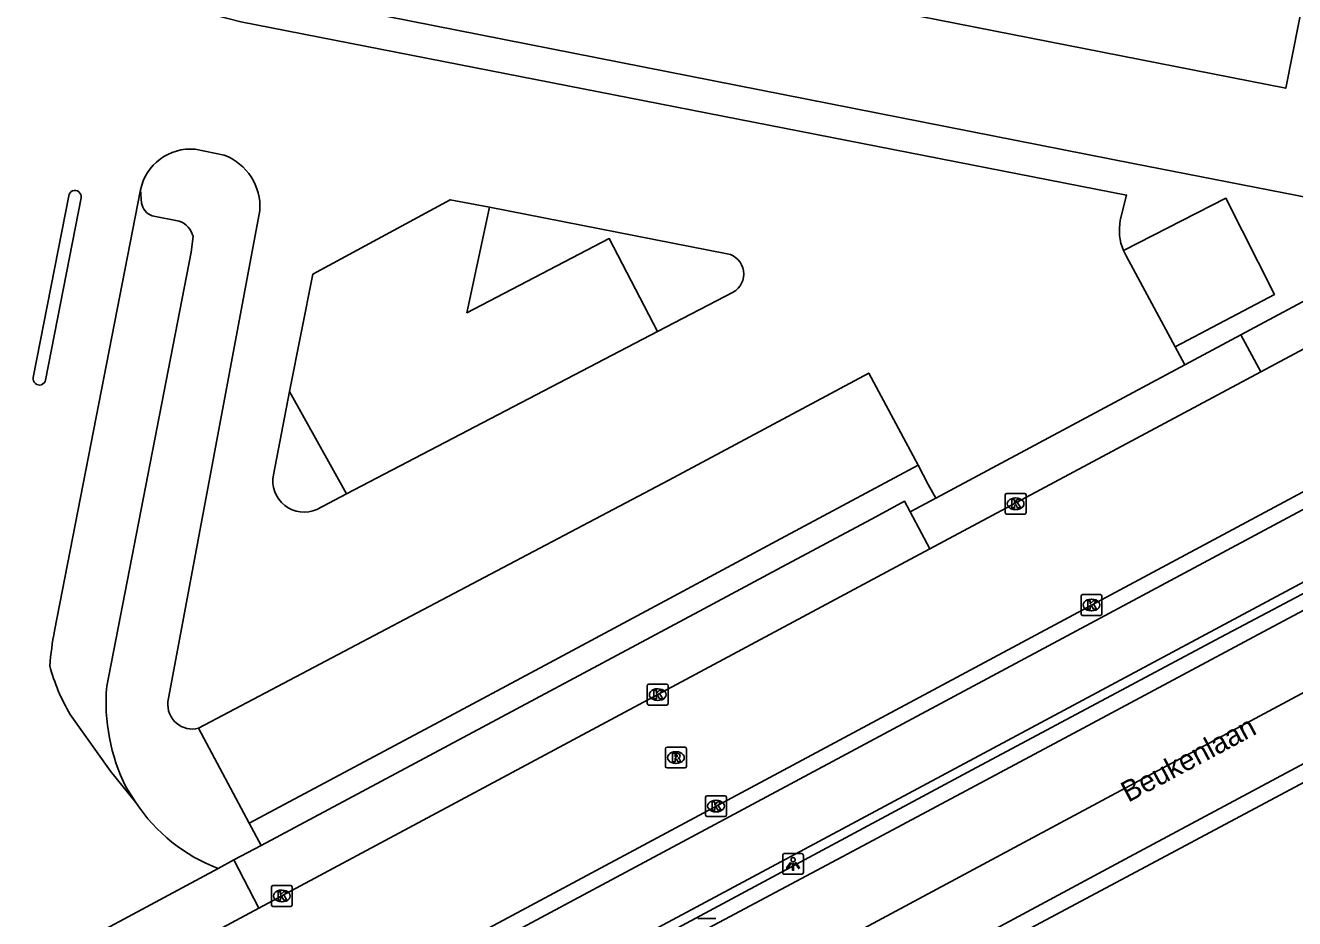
# Model space of a CAD drawing. Extents: x 158797 to 159887, y 384318 to 385255.
# Drawn here: x 159597.2 to 159658.1, y 384405.2 to 384448.1 of the extents above; entities that cross this region are included whole.
import ezdxf

# ---------------------------------------------------------------- set-up
doc = ezdxf.new("R2010")
doc.units = 0
for name, color, linetype in [('IMGEO_Berm_open', 7, 'Continuous'), ('IMGEO_Fietspad_gesloten', 7, 'Continuous'), ('IMGEO_Kolk', 7, 'Continuous'), ('IMGEO_Lichtpunt', 7, 'Continuous'), ('IMGEO_Openbare_ruimte_label', 7, 'Continuous'), ('IMGEO_Pand', 7, 'Continuous'), ('IMGEO_Parkeervlak_open', 7, 'Continuous'), ('IMGEO_Rijbaan_lokaal_gesloten', 7, 'Continuous'), ('IMGEO_Rijbaan_regionaal_gesloten', 7, 'Continuous'), ('IMGEO_Rioolput', 7, 'Continuous'), ('IMGEO_Voetpad_open', 7, 'Continuous')]:
    doc.layers.add(name, color=color, linetype=linetype)

msp = doc.modelspace()

# ---------------------------------------------------------------- linework, layer by layer
at = {"layer": 'IMGEO_Berm_open'}
msp.add_lwpolyline([(159693.288, 384438.625), (159692.958, 384439.23), (159683.971, 384434.448), (159672.561, 384428.328), (159664.238, 384423.844), (159654.268, 384418.57), (159642.609, 384412.337), (159624.993, 384402.897), (159622.895, 384401.766), (159617.171, 384398.703), (159613.053, 384396.512)], dxfattribs=at)
at = {"layer": 'IMGEO_Fietspad_gesloten'}
for points in [[(159707.394, 384451.026), (159691.341, 384442.43), (159554.532, 384369.175), (159553.562, 384368.656)], [(159705.22, 384446.356), (159692.734, 384439.673), (159612.839, 384396.912)]]:
    msp.add_lwpolyline(points, dxfattribs=at)
at = {"layer": 'IMGEO_Kolk'}
for p, q in [((159644.191, 384424.683), (159644.191, 384425.535)), ((159644.266, 384425.609), (159645.118, 384425.609)), ((159645.192, 384425.535), (159645.192, 384424.683)), ((159644.679, 384425.389), (159644.704, 384425.389)), ((159645.118, 384424.609), (159644.266, 384424.609)), ((159644.702, 384424.829), (159644.677, 384424.829)), ((159647.831, 384419.827), (159647.831, 384420.679)), ((159647.906, 384420.753), (159648.758, 384420.753)), ((159648.832, 384420.679), (159648.832, 384419.827)), ((159648.342, 384419.973), (159648.317, 384419.973)), ((159648.319, 384420.533), (159648.344, 384420.533)), ((159648.758, 384419.753), (159647.906, 384419.753)), ((159627.019, 384415.527), (159627.019, 384416.379)), ((159627.094, 384416.453), (159627.946, 384416.453)), ((159628.02, 384416.379), (159628.02, 384415.527)), ((159627.507, 384416.233), (159627.532, 384416.233)), ((159627.946, 384415.453), (159627.094, 384415.453)), ((159627.53, 384415.673), (159627.505, 384415.673)), ((159629.815, 384410.178), (159629.815, 384411.03)), ((159629.89, 384411.104), (159630.742, 384411.104)), ((159630.303, 384410.884), (159630.328, 384410.884)), ((159630.816, 384411.03), (159630.816, 384410.178)), ((159630.326, 384410.324), (159630.301, 384410.324)), ((159630.742, 384410.104), (159629.89, 384410.104)), ((159608.982, 384405.867), (159608.982, 384406.719)), ((159609.057, 384406.793), (159609.909, 384406.793)), ((159609.983, 384406.719), (159609.983, 384405.867)), ((159609.493, 384406.013), (159609.468, 384406.013)), ((159609.47, 384406.573), (159609.495, 384406.573)), ((159609.909, 384405.793), (159609.057, 384405.793)), ((159629.45, 384405.206), (159630.302, 384405.206))]:
    msp.add_line(p, q, dxfattribs=at)
for points in [[(159644.191, 384424.683), (159644.191, 384425.535)], [(159644.266, 384425.609), (159645.118, 384425.609)], [(159645.192, 384425.535), (159645.192, 384424.683)], [(159644.512, 384425.309), (159644.635, 384425.309), (159644.635, 384425.158), (159644.765, 384425.309), (159644.929, 384425.309), (159644.783, 384425.158), (159644.936, 384424.909), (159644.784, 384424.909), (159644.699, 384425.073), (159644.635, 384425.006), (159644.635, 384424.909), (159644.512, 384424.909), (159644.512, 384425.309)], [(159645.118, 384424.609), (159644.266, 384424.609)], [(159647.831, 384419.827), (159647.831, 384420.679)], [(159647.906, 384420.753), (159648.758, 384420.753)], [(159648.832, 384420.679), (159648.832, 384419.827)], [(159648.152, 384420.453), (159648.275, 384420.453), (159648.275, 384420.302), (159648.405, 384420.453), (159648.569, 384420.453), (159648.423, 384420.302), (159648.576, 384420.053), (159648.424, 384420.053), (159648.339, 384420.217), (159648.275, 384420.15), (159648.275, 384420.053), (159648.152, 384420.053), (159648.152, 384420.453)], [(159648.758, 384419.753), (159647.906, 384419.753)], [(159627.019, 384415.527), (159627.019, 384416.379)], [(159627.094, 384416.453), (159627.946, 384416.453)], [(159628.02, 384416.379), (159628.02, 384415.527)], [(159627.34, 384416.153), (159627.463, 384416.153), (159627.463, 384416.002), (159627.593, 384416.153), (159627.757, 384416.153), (159627.611, 384416.002), (159627.764, 384415.753), (159627.612, 384415.753), (159627.527, 384415.917), (159627.463, 384415.85), (159627.463, 384415.753), (159627.34, 384415.753), (159627.34, 384416.153)], [(159627.946, 384415.453), (159627.094, 384415.453)], [(159629.815, 384410.178), (159629.815, 384411.03)], [(159629.89, 384411.104), (159630.742, 384411.104)], [(159630.816, 384411.03), (159630.816, 384410.178)], [(159630.136, 384410.804), (159630.259, 384410.804), (159630.259, 384410.653), (159630.389, 384410.804), (159630.553, 384410.804), (159630.407, 384410.653), (159630.56, 384410.404), (159630.408, 384410.404), (159630.323, 384410.568), (159630.259, 384410.501), (159630.259, 384410.404), (159630.136, 384410.404), (159630.136, 384410.804)], [(159630.742, 384410.104), (159629.89, 384410.104)], [(159608.982, 384405.867), (159608.982, 384406.719)], [(159609.057, 384406.793), (159609.909, 384406.793)], [(159609.983, 384406.719), (159609.983, 384405.867)], [(159609.303, 384406.493), (159609.426, 384406.493), (159609.426, 384406.342), (159609.556, 384406.493), (159609.72, 384406.493), (159609.574, 384406.342), (159609.727, 384406.093), (159609.575, 384406.093), (159609.49, 384406.257), (159609.426, 384406.19), (159609.426, 384406.093), (159609.303, 384406.093), (159609.303, 384406.493)], [(159609.909, 384405.793), (159609.057, 384405.793)], [(159629.45, 384405.206), (159630.302, 384405.206)]]:
    msp.add_lwpolyline(points, dxfattribs=at)
for centre, start, end in [((159644.268, 384425.533), 91.55205, 178.44795), ((159644.268, 384425.533), 91.55205, 178.44795), ((159645.116, 384425.533), 1.55205, 88.44795), ((159645.116, 384425.533), 1.55205, 88.44795), ((159644.268, 384424.685), 181.55205, 268.44795), ((159644.268, 384424.685), 181.55205, 268.44795), ((159645.116, 384424.685), 271.55205, 358.44795), ((159645.116, 384424.685), 271.55205, 358.44795), ((159647.908, 384420.677), 91.55205, 178.44795), ((159647.908, 384420.677), 91.55205, 178.44795), ((159648.756, 384420.677), 1.55205, 88.44795), ((159648.756, 384420.677), 1.55205, 88.44795), ((159647.908, 384419.829), 181.55205, 268.44795), ((159647.908, 384419.829), 181.55205, 268.44795), ((159648.756, 384419.829), 271.55205, 358.44795), ((159648.756, 384419.829), 271.55205, 358.44795), ((159627.096, 384416.377), 91.55205, 178.44795), ((159627.096, 384416.377), 91.55205, 178.44795), ((159627.944, 384416.377), 1.55205, 88.44795), ((159627.944, 384416.377), 1.55205, 88.44795), ((159627.096, 384415.529), 181.55205, 268.44795), ((159627.096, 384415.529), 181.55205, 268.44795), ((159627.944, 384415.529), 271.55205, 358.44795), ((159627.944, 384415.529), 271.55205, 358.44795), ((159629.892, 384411.028), 91.55205, 178.44795), ((159629.892, 384411.028), 91.55205, 178.44795), ((159630.74, 384411.028), 1.55205, 88.44795), ((159630.74, 384411.028), 1.55205, 88.44795), ((159629.892, 384410.18), 181.55205, 268.44795), ((159629.892, 384410.18), 181.55205, 268.44795), ((159630.74, 384410.18), 271.55205, 358.44795), ((159630.74, 384410.18), 271.55205, 358.44795), ((159609.059, 384406.717), 91.55205, 178.44795), ((159609.059, 384406.717), 91.55205, 178.44795), ((159609.907, 384406.717), 1.55205, 88.44795), ((159609.907, 384406.717), 1.55205, 88.44795), ((159609.059, 384405.869), 181.55205, 268.44795), ((159609.059, 384405.869), 181.55205, 268.44795), ((159609.907, 384405.869), 271.55205, 358.44795), ((159609.907, 384405.869), 271.55205, 358.44795)]:
    msp.add_arc(centre, 0.0765, start, end, dxfattribs=at)
for centre, major_axis, ratio, start_param, end_param in [((159644.678, 384425.109), (-0.387, 0.002), 0.722429, 4.712389, 7.853982), ((159644.703, 384425.109), (-0.39, 0.002), 0.717154, 1.570796, 4.712389), ((159648.318, 384420.253), (-0.387, 0.002), 0.722429, 4.712389, 7.853982), ((159648.343, 384420.253), (-0.39, 0.002), 0.717154, 1.570796, 4.712389), ((159627.506, 384415.953), (-0.387, 0.002), 0.722429, 4.712389, 7.853982), ((159627.531, 384415.953), (-0.39, 0.002), 0.717154, 1.570796, 4.712389), ((159630.302, 384410.604), (-0.387, 0.002), 0.722429, 4.712389, 7.853982), ((159630.327, 384410.604), (-0.39, 0.002), 0.717154, 1.570796, 4.712389), ((159609.469, 384406.293), (-0.387, 0.002), 0.722429, 4.712389, 7.853982), ((159609.494, 384406.293), (-0.39, 0.002), 0.717154, 1.570796, 4.712389)]:
    msp.add_ellipse(centre, major_axis=major_axis, ratio=ratio, start_param=start_param, end_param=end_param, dxfattribs=at)
at = {"layer": 'IMGEO_Lichtpunt'}
for p, q in [((159633.516, 384408.236), (159633.516, 384407.429)), ((159633.516, 384408.236), (159633.516, 384407.429)), ((159634.418, 384408.331), (159633.61, 384408.331)), ((159634.418, 384408.331), (159633.61, 384408.331)), ((159634.512, 384407.429), (159634.512, 384408.236)), ((159634.512, 384407.429), (159634.512, 384408.236)), ((159633.61, 384407.335), (159634.418, 384407.335)), ((159633.61, 384407.335), (159634.418, 384407.335))]:
    msp.add_line(p, q, dxfattribs=at)
for points in [[(159633.89, 384407.9), (159633.929, 384407.872), (159633.741, 384407.61), (159633.703, 384407.637), (159633.89, 384407.9)], [(159633.992, 384407.852), (159634.039, 384407.852), (159634.039, 384407.53), (159633.992, 384407.53), (159633.992, 384407.852)], [(159634.102, 384407.872), (159634.14, 384407.899), (159634.327, 384407.637), (159634.288, 384407.609), (159634.102, 384407.872)]]:
    msp.add_lwpolyline(points, dxfattribs=at)
msp.add_circle((159634.015, 384408.034), 0.0994, dxfattribs=at)
for centre, start, end in [((159633.61, 384408.236), 90, 180), ((159633.61, 384408.236), 90, 180), ((159634.418, 384408.236), 0, 90), ((159634.418, 384408.236), 0, 90), ((159633.61, 384407.429), 180, 270), ((159633.61, 384407.429), 180, 270), ((159634.418, 384407.429), 270, 0), ((159634.418, 384407.429), 270, 360)]:
    msp.add_arc(centre, 0.0946, start, end, dxfattribs=at)
at = {"layer": 'IMGEO_Pand'}
msp.add_lwpolyline([(159615.168, 384493.218), (159631.646, 384489.94), (159631.594, 384489.43), (159642.299, 384487.34), (159642.371, 384487.828), (159663.172, 384483.741), (159663.062, 384483.15), (159665.104, 384482.719), (159657.652, 384445.044), (159634.856, 384449.536), (159634.884, 384450.102), (159624.284, 384452.245), (159624.125, 384451.684), (159608.374, 384454.809), (159607.652, 384454.952)], dxfattribs=at)
at = {"layer": 'IMGEO_Parkeervlak_open'}
msp.add_lwpolyline([(159640.014, 384426.956), (159633.201, 384423.308), (159628.746, 384420.922), (159622.319, 384417.481), (159616.58, 384414.408), (159607.921, 384409.781)], dxfattribs=at)
at = {"layer": 'IMGEO_Rijbaan_lokaal_gesloten'}
for points in [[(159553.184, 384369.293), (159691, 384443.105), (159706.671, 384451.498)], [(159649.715, 384438.714), (159650.018, 384439.921), (159607.516, 384448.232), (159606.273, 384448.548)], [(159656.463, 384431.445), (159663.602, 384435.266), (159667.341, 384437.251), (159683.468, 384445.886)], [(159605.321, 384442.122), (159606.717, 384441.837)], [(159598.577, 384419.017), (159602.701, 384440.173)], [(159597.56, 384431.163), (159599.256, 384439.891)], [(159599.848, 384439.793), (159598.148, 384431.047)], [(159609.858, 384430.49), (159610.974, 384436.129), (159617.567, 384439.692), (159619.441, 384439.334)], [(159608.429, 384439.174), (159604.02, 384415.601)], [(159619.441, 384439.334), (159630.857, 384437.108)], [(159652.339, 384432.641), (159649.99, 384437.008), (159649.866, 384437.26)], [(159631.136, 384435.258), (159627.514, 384433.369)], [(159627.514, 384433.369), (159612.594, 384425.584)], [(159652.805, 384431.774), (159652.339, 384432.641)], [(159640.859, 384425.377), (159652.805, 384431.774)], [(159605.487, 384414.336), (159615.678, 384419.713), (159628.056, 384426.244), (159637.645, 384431.379), (159640.014, 384426.956)], [(159640.576, 384422.941), (159656.463, 384431.445)], [(159609.082, 384426.497), (159609.858, 384430.49)], [(159640.014, 384426.956), (159640.503, 384426.042), (159640.859, 384425.377)], [(159612.594, 384425.584), (159611.17, 384424.84)], [(159640.576, 384422.941), (159639.863, 384422.559), (159627.52, 384415.953), (159609.483, 384406.293), (159608.385, 384405.705)], [(159602.483, 384410.773), (159601.258, 384412.276), (159599.333, 384415.004)], [(159588.06, 384397.767), (159606.423, 384407.612)], [(159578.043, 384389.447), (159608.385, 384405.705)]]:
    msp.add_lwpolyline(points, dxfattribs=at)
for centre, radius, start, end in [((159605.114, 384439.664), 2.466, 85.19294, 168.09767), ((159605.774, 384439.349), 2.661, 356.23152, 69.24111), ((159599.552, 384439.842), 0.3, 350.60047, 170.60047), ((159652.187, 384438.236), 2.518, 169.05592, 202.80207), ((159630.646, 384436.13), 1, 299.34748, 77.80491), ((159597.854, 384431.105), 0.3, 168.84006, 348.84006), ((159610.555, 384426.209), 1.501, 168.91852, 294.21169), ((159614.072, 384416.048), 15.777, 169.15492, 175.3117), ((159607.169, 384419.686), 9.129, 194.90487, 210.85679), ((159605.191, 384415.475), 1.177, 173.87632, 284.58102), ((159609.335, 384415.278), 8.2, 213.32244, 249.19851)]:
    msp.add_arc(centre, radius, start, end, dxfattribs=at)
at = {"layer": 'IMGEO_Rijbaan_regionaal_gesloten'}
for points in [[(159880.669, 384532.909), (159875.798, 384530.374), (159847.424, 384515.674), (159804.811, 384493.696), (159779.976, 384480.85), (159750.919, 384465.55), (159708.655, 384442.945), (159694.585, 384435.384), (159645.738, 384409.21), (159615.068, 384392.753)], [(159616.488, 384390.102), (159630.958, 384397.851), (159650.153, 384408.169), (159667.67, 384417.548), (159686.549, 384427.613), (159696.214, 384432.791), (159709.47, 384439.893), (159725.249, 384448.362), (159745.061, 384458.917), (159759.449, 384466.649), (159775.497, 384475.211), (159791.41, 384483.447), (159811.928, 384494.056), (159823.458, 384500), (159870.864, 384524.44), (159874.443, 384526.273), (159882.662, 384530.596)], [(159883.694, 384529.35), (159881.307, 384528.22), (159875.887, 384525.604), (159825.453, 384500), (159812.356, 384493.351), (159791.799, 384482.795), (159777.564, 384475.395), (159744.535, 384457.751), (159731.675, 384450.855), (159717.186, 384443.101), (159697.88, 384432.802), (159696.562, 384432.097), (159679.569, 384423.013), (159661.921, 384413.563), (159644.473, 384404.254), (159631.206, 384397.094), (159616.87, 384389.389)], [(159693.288, 384438.625), (159687.108, 384435.294), (159673.007, 384427.734), (159656.81, 384419.099), (159647.237, 384413.981), (159637.604, 384408.821), (159626.551, 384402.935), (159617.694, 384398.165), (159613.635, 384395.988), (159613.401, 384395.863)]]:
    msp.add_lwpolyline(points, dxfattribs=at)
at = {"layer": 'IMGEO_Rioolput'}
for p, q in [((159627.893, 384412.507), (159627.893, 384413.359)), ((159627.968, 384413.433), (159628.82, 384413.433)), ((159628.894, 384413.359), (159628.894, 384412.507)), ((159628.381, 384413.213), (159628.406, 384413.213)), ((159628.82, 384412.433), (159627.968, 384412.433)), ((159628.404, 384412.653), (159628.379, 384412.653))]:
    msp.add_line(p, q, dxfattribs=at)
for points in [[(159627.893, 384412.507), (159627.893, 384413.359)], [(159627.968, 384413.433), (159628.82, 384413.433)], [(159628.894, 384413.359), (159628.894, 384412.507)], [(159628.482, 384413.131), (159628.23, 384413.133), (159628.23, 384412.733)], [(159628.23, 384412.733), (159628.354, 384412.733), (159628.354, 384412.895), (159628.365, 384412.895)], [(159628.408, 384413.052), (159628.354, 384413.052), (159628.354, 384412.971)], [(159628.354, 384412.971), (159628.406, 384412.971)], [(159628.412, 384412.866), (159628.483, 384412.733), (159628.623, 384412.733), (159628.558, 384412.859)], [(159628.82, 384412.433), (159627.968, 384412.433)]]:
    msp.add_lwpolyline(points, dxfattribs=at)
for centre, radius, start, end in [((159627.97, 384413.357), 0.0765, 91.55205, 178.44795), ((159627.97, 384413.357), 0.0765, 91.55205, 178.44795), ((159628.818, 384413.357), 0.0765, 1.55205, 88.44795), ((159628.818, 384413.357), 0.0765, 1.55205, 88.44795), ((159628.364, 384412.842), 0.0533, 26.02933, 88.69889), ((159628.39, 384413.16), 0.19, 274.7715, 282.96867), ((159628.414, 384412.956), 0.0964, 77.00612, 93.18647), ((159628.428, 384413.013), 0.0378, 276.66336, 79.67722), ((159628.481, 384413.021), 0.109, 350.36119, 89.41601), ((159628.479, 384413.021), 0.112, 277.58423, 350.98172), ((159628.463, 384412.806), 0.108, 29.51342, 73.79051), ((159627.97, 384412.509), 0.0765, 181.55205, 268.44795), ((159627.97, 384412.509), 0.0765, 181.55205, 268.44795), ((159628.818, 384412.509), 0.0765, 271.55205, 358.44795), ((159628.818, 384412.509), 0.0765, 271.55205, 358.44795)]:
    msp.add_arc(centre, radius, start, end, dxfattribs=at)
for centre, major_axis, ratio, start_param, end_param in [((159628.38, 384412.933), (-0.387, 0.002), 0.722429, 4.712389, 7.853982), ((159628.405, 384412.933), (-0.39, 0.002), 0.717154, 1.570796, 4.712389)]:
    msp.add_ellipse(centre, major_axis=major_axis, ratio=ratio, start_param=start_param, end_param=end_param, dxfattribs=at)
at = {"layer": 'IMGEO_Voetpad_open'}
for points in [[(159607.652, 384454.952), (159606.689, 384450.048), (159650.339, 384441.442), (159664.679, 384438.637), (159682.172, 384447.751), (159682.698, 384450.091), (159679.597, 384455.98), (159680.012, 384456.195)], [(159683.461, 384448.173), (159666.374, 384439.04), (159655.504, 384433.219)], [(159602.752, 384439.537), (159602.701, 384440.173)], [(159652.339, 384432.641), (159657.107, 384435.157), (159654.782, 384439.768), (159649.866, 384437.26)], [(159604.564, 384438.67), (159603.262, 384438.931)], [(159627.514, 384433.369), (159625.193, 384437.831), (159618.364, 384434.278), (159619.441, 384439.334)], [(159601.079, 384416.355), (159605.141, 384437.184), (159605.231, 384437.939)], [(159655.504, 384433.219), (159652.805, 384431.774)], [(159655.504, 384433.219), (159656.463, 384431.445)], [(159609.858, 384430.49), (159612.594, 384425.584)], [(159608.49, 384408.717), (159629.737, 384420.076), (159633.252, 384421.955), (159637.986, 384424.489), (159639.366, 384425.228), (159639.63, 384424.719)], [(159640.859, 384425.377), (159639.63, 384424.719)], [(159639.63, 384424.719), (159640.576, 384422.941)], [(159607.921, 384409.781), (159605.487, 384414.336)], [(159602.483, 384410.773), (159601.996, 384411.522)], [(159608.49, 384408.717), (159607.921, 384409.781)], [(159607.186, 384408.02), (159608.49, 384408.717)], [(159607.186, 384408.02), (159606.423, 384407.612)], [(159608.385, 384405.705), (159607.186, 384408.02)]]:
    msp.add_lwpolyline(points, dxfattribs=at)
for centre, radius, start, end in [((159603.514, 384439.661), 0.772, 189.21364, 250.95323), ((159604.146, 384437.619), 1.131, 16.43301, 68.32468), ((159610.346, 384415.61), 9.297, 175.40263, 206.08424)]:
    msp.add_arc(centre, radius, start, end, dxfattribs=at)

# ---------------------------------------------------------------- texts
at = {"layer": 'IMGEO_Openbare_ruimte_label'}
msp.add_text('Beukenlaan', height=1, rotation=28.10282, dxfattribs=at).set_placement((159650.095, 384410.764))

doc.saveas('drawing.dxf')
